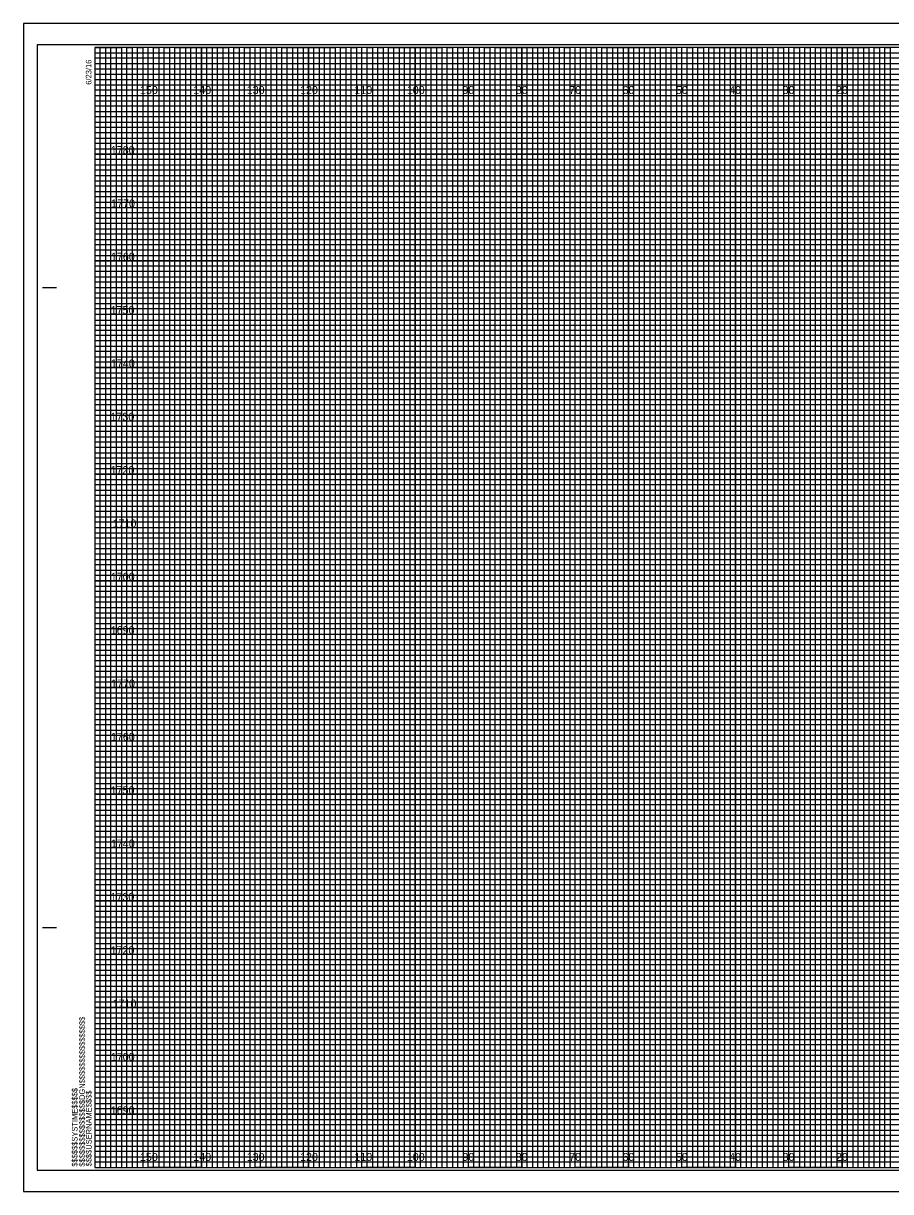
# Model space of a CAD drawing. Extents: x -13 to 1780, y -15 to 3284.
# Drawn here: x 1443.3 to 1605.8, y 205.2 to 424.2 of the extents above; entities that cross this region are included whole.
import ezdxf

# ---------------------------------------------------------------- set-up
doc = ezdxf.new("R2010")
doc.units = 0
for name, color, linetype in [('Prop Retaining Wall', 7, 'Continuous'), ('Prop SS Cut Line', 7, 'Continuous'), ('Prop SS Fill Line', 7, 'Continuous'), ('Prop SS Transition Line', 7, 'Continuous'), ('Prop XS Earthwork Shape', 7, 'Continuous'), ('Prop XS Noise Wall', 7, 'Continuous'), ('Prop XS Station Labels', 7, 'Continuous'), ('Raster_Level_0', 7, 'Continuous'), ('Scratch_Level_3', 7, 'Continuous'), ('Scratch_Level_7', 7, 'Continuous'), ('Typical Bridge Rail CELL', 7, 'Continuous')]:
    doc.layers.add(name, color=color, linetype=linetype)

msp = doc.modelspace()

# ---------------------------------------------------------------- linework, layer by layer
at = {"layer": 'Prop Retaining Wall'}
for p, q in [((1446.88, 374.71), (1449.38, 374.71)), ((1446.98, 374.71), (1449.48, 374.71)), ((1446.88, 254.71), (1449.38, 254.71)), ((1446.98, 254.71), (1449.48, 254.71)), ((1456.68, 209.71), (1456.68, 209.71)), ((1456.68, 209.71), (1456.68, 209.71)), ((1456.68, 209.71), (1456.68, 209.71)), ((1456.68, 209.71), (1456.68, 209.71)), ((1456.68, 209.71), (1456.68, 209.71)), ((1456.68, 209.71), (1456.68, 209.71)), ((1456.68, 209.71), (1456.68, 209.71))]:
    msp.add_line(p, q, dxfattribs=at)
msp.add_lwpolyline([(1776.68, 419.71), (1456.68, 419.71), (1456.68, 209.71), (1776.68, 209.71)], close=True, dxfattribs=at)
at = {"layer": 'Prop SS Cut Line'}
for points in [[(1456.68, 419.71), (1461.68, 419.71), (1461.68, 209.71), (1471.68, 209.71), (1471.68, 419.71), (1481.68, 419.71), (1481.68, 209.71), (1491.68, 209.71), (1491.68, 419.71), (1501.68, 419.71), (1501.68, 209.71), (1511.68, 209.71), (1511.68, 419.71), (1521.68, 419.71), (1521.68, 209.71), (1531.68, 209.71), (1531.68, 419.71), (1541.68, 419.71), (1541.68, 209.71), (1551.68, 209.71), (1551.68, 419.71), (1561.68, 419.71), (1561.68, 209.71), (1571.68, 209.71), (1571.68, 419.71), (1581.68, 419.71), (1581.68, 209.71), (1591.68, 209.71), (1591.68, 419.71), (1601.68, 419.71), (1601.68, 209.71), (1611.68, 209.71)], [(1456.68, 414.71), (1731.68, 414.71)], [(1456.68, 394.71), (1776.68, 394.71), (1776.68, 404.71), (1456.68, 404.71)], [(1456.68, 374.71), (1776.68, 374.71), (1776.68, 384.71), (1456.68, 384.71)], [(1456.68, 354.71), (1776.68, 354.71), (1776.68, 364.71), (1456.68, 364.71)], [(1456.68, 334.71), (1776.68, 334.71), (1776.68, 344.71), (1456.68, 344.71)], [(1456.68, 314.71), (1776.68, 314.71), (1776.68, 324.71), (1456.68, 324.71)], [(1456.68, 294.71), (1776.68, 294.71), (1776.68, 304.71), (1456.68, 304.71)], [(1456.68, 274.71), (1776.68, 274.71), (1776.68, 284.71), (1456.68, 284.71)], [(1456.68, 254.71), (1776.68, 254.71), (1776.68, 264.71), (1456.68, 264.71)], [(1456.68, 234.71), (1776.68, 234.71), (1776.68, 244.71), (1456.68, 244.71)], [(1456.68, 214.71), (1776.68, 214.71), (1776.68, 224.71), (1456.68, 224.71)]]:
    msp.add_lwpolyline(points, dxfattribs=at)
at = {"layer": 'Prop SS Fill Line'}
for p, q in [((1466.68, 419.71), (1456.68, 419.71)), ((1466.68, 209.71), (1466.68, 419.71)), ((1486.68, 419.71), (1476.68, 419.71)), ((1476.68, 419.71), (1476.68, 209.71)), ((1486.68, 209.71), (1486.68, 419.71)), ((1506.68, 419.71), (1496.68, 419.71)), ((1496.68, 419.71), (1496.68, 209.71)), ((1506.68, 209.71), (1506.68, 419.71)), ((1526.68, 419.71), (1516.68, 419.71)), ((1516.68, 419.71), (1516.68, 209.71)), ((1526.68, 209.71), (1526.68, 419.71)), ((1546.68, 419.71), (1536.68, 419.71)), ((1536.68, 419.71), (1536.68, 209.71)), ((1546.68, 209.71), (1546.68, 419.71)), ((1566.68, 419.71), (1556.68, 419.71)), ((1556.68, 419.71), (1556.68, 209.71)), ((1566.68, 209.71), (1566.68, 419.71)), ((1586.68, 419.71), (1576.68, 419.71)), ((1576.68, 419.71), (1576.68, 209.71)), ((1586.68, 209.71), (1586.68, 419.71)), ((1606.68, 419.71), (1596.68, 419.71)), ((1596.68, 419.71), (1596.68, 209.71)), ((1476.68, 209.71), (1466.68, 209.71)), ((1496.68, 209.71), (1486.68, 209.71)), ((1516.68, 209.71), (1506.68, 209.71)), ((1536.68, 209.71), (1526.68, 209.71)), ((1556.68, 209.71), (1546.68, 209.71)), ((1576.68, 209.71), (1566.68, 209.71)), ((1596.68, 209.71), (1586.68, 209.71))]:
    msp.add_line(p, q, dxfattribs=at)
for points in [[(1456.68, 409.71), (1776.68, 409.71), (1776.68, 399.71), (1456.68, 399.71)], [(1456.68, 389.71), (1776.68, 389.71), (1776.68, 379.71), (1456.68, 379.71)], [(1456.68, 369.71), (1776.68, 369.71), (1776.68, 359.71), (1456.68, 359.71)], [(1456.68, 349.71), (1776.68, 349.71), (1776.68, 339.71), (1456.68, 339.71)], [(1456.68, 329.71), (1776.68, 329.71), (1776.68, 319.71), (1456.68, 319.71)], [(1456.68, 309.71), (1776.68, 309.71), (1776.68, 299.71), (1456.68, 299.71)], [(1456.68, 289.71), (1776.68, 289.71), (1776.68, 279.71), (1456.68, 279.71)], [(1456.68, 269.71), (1776.68, 269.71), (1776.68, 259.71), (1456.68, 259.71)], [(1456.68, 249.71), (1776.68, 249.71), (1776.68, 239.71), (1456.68, 239.71)], [(1456.68, 229.71), (1776.68, 229.71), (1776.68, 219.71), (1456.68, 219.71)]]:
    msp.add_lwpolyline(points, dxfattribs=at)
at = {"layer": 'Prop SS Transition Line'}
for p, q in [((1456.68, 418.71), (1716.68, 418.71)), ((1716.68, 417.69), (1456.68, 417.69)), ((1456.68, 417.69), (1456.68, 416.71)), ((1456.68, 416.71), (1716.68, 416.71)), ((1716.68, 415.6), (1456.68, 415.6)), ((1456.68, 415.6), (1456.68, 413.71)), ((1456.68, 413.71), (1776.68, 413.71))]:
    msp.add_line(p, q, dxfattribs=at)
for points in [[(1456.68, 412.71), (1726.68, 412.71), (1776.68, 412.71), (1776.68, 411.71), (1456.68, 411.71)], [(1456.68, 410.71), (1776.68, 410.71), (1776.68, 408.71), (1456.68, 408.71)], [(1456.68, 407.71), (1776.68, 407.71), (1776.68, 406.71), (1456.68, 406.69)], [(1456.68, 405.71), (1776.68, 405.71), (1776.68, 403.71), (1456.68, 403.71)], [(1456.68, 402.71), (1776.68, 402.71), (1776.68, 401.71), (1456.68, 401.71)], [(1456.68, 400.71), (1776.68, 400.71), (1776.68, 398.71), (1456.68, 398.71)], [(1456.68, 397.71), (1776.68, 397.71), (1776.68, 396.71), (1456.68, 396.71)], [(1456.68, 395.71), (1776.68, 395.71), (1776.68, 393.71), (1456.68, 393.71)], [(1456.68, 392.71), (1776.68, 392.71), (1776.68, 391.71), (1456.68, 391.71)], [(1456.68, 390.71), (1776.68, 390.71), (1776.68, 388.71), (1456.68, 388.71)], [(1456.68, 387.71), (1776.68, 387.71), (1776.68, 386.71), (1456.68, 386.71)], [(1456.68, 385.71), (1776.68, 385.71), (1776.68, 383.66), (1776.68, 382.71), (1776.68, 381.71), (1456.68, 381.71)], [(1456.68, 383.71), (1776.68, 383.71), (1776.68, 382.71), (1456.68, 382.71)], [(1456.68, 380.71), (1776.68, 380.71), (1776.68, 378.71), (1456.68, 378.74)], [(1456.68, 378.74), (1776.68, 378.71), (1776.68, 377.71), (1456.68, 377.71)], [(1456.68, 376.71), (1776.68, 376.71), (1776.68, 375.71), (1456.68, 375.71)], [(1456.68, 373.71), (1776.68, 373.71), (1776.68, 372.71), (1456.68, 372.71)], [(1456.68, 371.71), (1776.68, 371.71), (1776.68, 370.71), (1456.68, 370.71)], [(1456.61, 368.6), (1776.68, 368.6), (1776.68, 367.59), (1456.61, 367.59)], [(1456.68, 366.71), (1776.68, 366.71), (1776.68, 365.71), (1456.68, 365.71)], [(1456.68, 363.71), (1776.68, 363.71), (1776.68, 362.71), (1456.68, 362.71)], [(1456.68, 361.71), (1776.68, 361.71), (1776.68, 360.71), (1456.68, 360.71)], [(1456.68, 358.71), (1776.68, 358.71), (1776.68, 357.71), (1456.68, 357.71)], [(1456.68, 356.71), (1776.68, 356.71), (1776.68, 355.71), (1456.68, 355.71)], [(1456.68, 353.71), (1776.68, 353.71), (1776.68, 352.71), (1456.68, 352.71)], [(1456.68, 351.71), (1776.68, 351.71), (1776.68, 350.71), (1456.68, 350.71)], [(1456.68, 348.71), (1776.68, 348.71), (1776.67, 347.69), (1456.68, 347.71)], [(1456.68, 346.71), (1776.68, 346.71), (1776.68, 345.71), (1456.68, 345.71)], [(1456.68, 343.71), (1776.68, 343.71), (1776.68, 342.71), (1456.68, 342.71)], [(1456.68, 341.71), (1776.68, 341.71), (1776.68, 340.71), (1456.68, 340.71)], [(1456.68, 338.71), (1776.68, 338.71), (1776.68, 337.71), (1456.68, 337.71)], [(1456.68, 336.71), (1776.68, 336.71), (1776.68, 335.71), (1456.68, 335.71)], [(1456.68, 333.71), (1776.68, 333.71), (1776.68, 332.71), (1456.68, 332.71)], [(1456.68, 331.71), (1776.68, 331.71), (1776.68, 330.71), (1456.68, 330.71)], [(1456.68, 328.71), (1776.68, 328.71), (1776.68, 327.71), (1456.68, 327.71)], [(1456.68, 326.7), (1776.75, 326.62), (1776.68, 325.71), (1456.68, 325.71)], [(1456.68, 323.71), (1776.68, 323.71), (1776.68, 322.71), (1456.68, 322.71)], [(1456.68, 321.71), (1776.68, 321.71), (1776.68, 320.71), (1456.68, 320.71)], [(1456.68, 318.71), (1776.68, 318.71), (1776.68, 317.71), (1456.68, 317.71)], [(1456.68, 316.71), (1776.68, 316.71), (1776.68, 315.71), (1456.68, 315.71)], [(1456.68, 313.71), (1776.68, 313.71), (1776.68, 312.71), (1456.68, 312.71)], [(1456.68, 311.71), (1776.68, 311.71), (1776.68, 310.71), (1456.68, 310.71)], [(1456.68, 308.71), (1776.68, 308.71), (1776.68, 307.71), (1456.68, 307.71)], [(1456.68, 306.71), (1776.68, 306.71), (1776.68, 305.71), (1456.68, 305.71)], [(1456.68, 303.71), (1776.68, 303.71), (1776.68, 302.71), (1456.68, 302.71)], [(1456.68, 301.71), (1776.68, 301.71), (1776.68, 300.71), (1456.68, 300.71)], [(1456.68, 298.71), (1776.68, 298.71), (1776.68, 297.71), (1456.68, 297.71)], [(1456.68, 296.71), (1776.68, 296.71), (1776.68, 295.71), (1456.68, 295.71)], [(1456.68, 293.71), (1776.68, 293.71), (1776.68, 292.71), (1456.68, 292.71)], [(1456.68, 291.71), (1776.68, 291.71), (1776.68, 290.71), (1456.68, 290.71)], [(1456.68, 288.71), (1776.68, 288.71), (1776.67, 287.69), (1456.68, 287.71)], [(1456.68, 286.71), (1776.68, 286.71), (1776.68, 285.71), (1456.68, 285.71)], [(1456.68, 283.71), (1776.68, 283.71), (1776.68, 282.71), (1456.68, 282.71)], [(1456.68, 281.71), (1776.68, 281.71), (1776.68, 280.71), (1456.68, 280.71)], [(1456.68, 278.71), (1776.68, 278.71), (1776.68, 277.71), (1456.68, 277.71)], [(1456.68, 276.71), (1776.68, 276.71), (1776.68, 275.71), (1456.68, 275.71)], [(1456.68, 273.71), (1776.68, 273.71), (1776.68, 272.71), (1456.68, 272.71)], [(1456.68, 271.71), (1776.68, 271.71), (1776.68, 270.71), (1456.68, 270.71)], [(1456.68, 268.71), (1776.68, 268.71), (1776.68, 267.71), (1456.68, 267.71)], [(1456.68, 266.7), (1776.75, 266.62), (1776.68, 265.71), (1456.68, 265.71)], [(1456.68, 263.71), (1776.68, 263.71), (1776.68, 262.71), (1456.68, 262.71)], [(1456.68, 261.71), (1776.68, 261.71), (1776.68, 260.71), (1456.68, 260.71)], [(1456.68, 258.71), (1776.68, 258.71), (1776.68, 257.71), (1456.68, 257.71)], [(1456.68, 256.71), (1776.68, 256.71), (1776.68, 255.71), (1456.68, 255.71)], [(1456.68, 253.71), (1776.68, 253.71), (1776.68, 252.71), (1456.68, 252.71)], [(1456.68, 251.71), (1776.68, 251.71), (1776.68, 250.71), (1456.68, 250.71)], [(1456.68, 248.71), (1776.68, 248.71), (1776.68, 247.71), (1456.68, 247.71)], [(1456.68, 246.71), (1776.68, 246.71), (1776.68, 245.71), (1456.68, 245.71)], [(1456.68, 243.71), (1776.68, 243.71), (1776.68, 242.71), (1456.68, 242.71)], [(1456.68, 241.71), (1776.68, 241.71), (1776.68, 240.71), (1456.68, 240.71)], [(1456.68, 238.71), (1776.68, 238.71), (1776.68, 237.71), (1456.68, 237.71)], [(1456.68, 236.71), (1776.68, 236.71), (1776.68, 235.71), (1456.68, 235.71)], [(1456.68, 233.71), (1776.68, 233.71), (1776.68, 232.71), (1456.68, 232.71)], [(1456.68, 231.71), (1776.68, 231.71), (1776.68, 230.71), (1456.68, 230.71)], [(1456.68, 228.71), (1776.68, 228.71), (1776.68, 227.71), (1456.68, 227.71)], [(1456.68, 226.71), (1776.68, 226.71), (1776.68, 225.71), (1456.68, 225.71)], [(1456.68, 223.71), (1776.68, 223.71), (1776.68, 222.71), (1456.68, 222.71)], [(1456.68, 221.71), (1776.68, 221.71), (1776.68, 220.71), (1456.68, 220.71)], [(1456.68, 218.71), (1776.68, 218.71), (1776.68, 217.71), (1456.68, 217.71)], [(1456.68, 216.71), (1776.68, 216.71), (1776.68, 215.71), (1456.68, 215.71)], [(1456.68, 213.71), (1776.68, 213.71), (1776.68, 212.71), (1456.68, 212.71)], [(1456.68, 211.71), (1776.68, 211.71), (1776.68, 210.71), (1456.68, 210.71)]]:
    msp.add_lwpolyline(points, dxfattribs=at)
at = {"layer": 'Prop XS Earthwork Shape'}
msp.add_lwpolyline([(1443.28, 205.21), (1779.98, 205.21), (1779.98, 424.21), (1443.28, 424.21)], close=True, dxfattribs=at)
at = {"layer": 'Prop XS Noise Wall'}
for p, q in [((1466.68, 209.71), (1466.68, 419.71)), ((1476.68, 209.71), (1476.68, 419.71)), ((1486.68, 209.71), (1486.68, 419.71)), ((1496.68, 209.71), (1496.68, 419.71)), ((1506.68, 209.71), (1506.68, 419.71)), ((1516.68, 209.71), (1516.68, 419.71)), ((1526.68, 209.71), (1526.68, 419.71)), ((1536.68, 209.71), (1536.68, 419.71)), ((1546.68, 209.71), (1546.68, 419.71)), ((1556.68, 209.71), (1556.68, 419.71)), ((1566.68, 209.71), (1566.68, 419.71)), ((1576.68, 209.71), (1576.68, 419.71)), ((1586.68, 209.71), (1586.68, 419.71)), ((1596.68, 209.71), (1596.68, 419.71)), ((1456.68, 409.71), (1776.68, 409.71)), ((1456.68, 399.71), (1776.68, 399.71)), ((1456.68, 389.71), (1776.68, 389.71)), ((1456.68, 379.71), (1776.68, 379.71)), ((1456.68, 369.71), (1776.68, 369.71)), ((1456.68, 359.71), (1776.68, 359.71)), ((1456.68, 349.71), (1776.68, 349.71)), ((1456.68, 339.71), (1776.68, 339.71)), ((1456.68, 329.71), (1776.68, 329.71)), ((1456.68, 319.71), (1776.68, 319.71)), ((1456.68, 309.71), (1776.68, 309.71)), ((1456.68, 299.71), (1776.68, 299.71)), ((1456.68, 289.71), (1776.68, 289.71)), ((1456.68, 279.71), (1776.68, 279.71)), ((1456.68, 269.71), (1776.68, 269.71)), ((1456.68, 259.71), (1776.68, 259.71)), ((1456.68, 249.71), (1776.68, 249.71)), ((1456.68, 239.71), (1776.68, 239.71)), ((1456.68, 229.71), (1776.68, 229.71)), ((1456.68, 219.71), (1776.68, 219.71))]:
    msp.add_line(p, q, dxfattribs=at)
at = {"layer": 'Prop XS Station Labels'}
for p, q in [((1779.98, 424.21), (1443.28, 424.21)), ((1443.28, 424.21), (1443.28, 205.21)), ((1443.28, 205.21), (1779.98, 205.21))]:
    msp.add_line(p, q, dxfattribs=at)
at = {"layer": 'Scratch_Level_7'}
msp.add_lwpolyline([(1445.88, 209.21), (1779.08, 209.21), (1779.08, 420.21), (1445.88, 420.21)], close=True, dxfattribs=at)
at = {"layer": 'Typical Bridge Rail CELL'}
for points in [[(1456.68, 209.71), (1457.68, 209.71), (1457.68, 419.71), (1458.68, 419.71), (1458.68, 209.71)], [(1458.68, 209.71), (1459.68, 209.71), (1459.68, 419.71), (1460.68, 419.71), (1460.68, 209.71)], [(1461.68, 209.71), (1462.68, 209.71), (1462.68, 419.71), (1463.68, 419.71), (1463.68, 209.71)], [(1463.68, 209.71), (1464.68, 209.71), (1464.68, 419.71), (1465.68, 419.71), (1465.68, 209.71)], [(1466.68, 209.71), (1467.68, 209.71), (1467.68, 419.71), (1468.68, 419.71), (1468.68, 209.71)], [(1468.68, 209.71), (1469.68, 209.71), (1469.68, 419.71), (1470.68, 419.71), (1470.68, 209.71)], [(1471.68, 209.71), (1472.68, 209.71), (1472.68, 419.71), (1473.68, 419.71), (1473.68, 209.71)], [(1473.68, 209.71), (1474.68, 209.71), (1474.68, 419.71), (1475.68, 419.71), (1475.68, 209.71)], [(1476.68, 209.71), (1477.68, 209.71), (1477.68, 419.71), (1478.68, 419.71), (1478.68, 209.71)], [(1478.68, 209.71), (1479.68, 209.71), (1479.68, 419.71), (1480.68, 419.71), (1480.68, 209.71)], [(1481.68, 209.71), (1482.68, 209.71), (1482.68, 419.71), (1483.68, 419.71), (1483.68, 209.71)], [(1483.68, 209.71), (1484.68, 209.71), (1484.68, 419.71), (1485.68, 419.71), (1485.68, 209.71)], [(1486.68, 209.71), (1487.68, 209.71), (1487.68, 419.71), (1488.68, 419.71), (1488.68, 209.71)], [(1488.68, 209.71), (1489.68, 209.71), (1489.68, 419.71), (1490.68, 419.71), (1490.68, 209.71)], [(1491.68, 209.71), (1492.68, 209.71), (1492.68, 419.71), (1493.68, 419.71), (1493.68, 209.71)], [(1493.68, 209.71), (1494.68, 209.71), (1494.68, 419.71), (1495.68, 419.71), (1495.68, 209.71)], [(1496.68, 209.71), (1497.68, 209.71), (1497.68, 419.71), (1498.68, 419.71), (1498.68, 209.71)], [(1498.68, 209.71), (1499.68, 209.71), (1499.68, 419.71), (1500.68, 419.71), (1500.68, 209.71)], [(1501.68, 209.71), (1502.68, 209.71), (1502.68, 419.71), (1503.68, 419.71), (1503.68, 209.71)], [(1503.68, 209.71), (1504.68, 209.71), (1504.68, 419.71), (1505.68, 419.71), (1505.68, 209.71)], [(1506.68, 209.71), (1507.68, 209.71), (1507.68, 419.71), (1508.68, 419.71), (1508.68, 209.71)], [(1508.68, 209.71), (1509.68, 209.71), (1509.68, 419.71), (1510.68, 419.71), (1510.68, 209.71)], [(1511.68, 209.71), (1512.68, 209.71), (1512.68, 419.71), (1513.68, 419.71), (1513.68, 209.71)], [(1513.68, 209.71), (1514.68, 209.71), (1514.68, 419.71), (1515.68, 419.71), (1515.68, 209.71)], [(1516.68, 209.71), (1517.68, 209.71), (1517.68, 419.71), (1518.68, 419.71), (1518.68, 209.71)], [(1518.68, 209.71), (1519.68, 209.71), (1519.68, 419.71), (1520.68, 419.71), (1520.68, 209.71)], [(1521.68, 209.71), (1522.68, 209.71), (1522.68, 419.71), (1523.68, 419.71), (1523.68, 209.71)], [(1523.68, 209.71), (1524.68, 209.71), (1524.68, 419.71), (1525.68, 419.71), (1525.68, 209.71)], [(1526.68, 209.71), (1527.68, 209.71), (1527.68, 419.71), (1528.68, 419.71), (1528.68, 209.71)], [(1528.68, 209.71), (1529.68, 209.71), (1529.68, 419.71), (1530.68, 419.71), (1530.68, 209.71)], [(1531.68, 209.71), (1532.68, 209.71), (1532.68, 419.71), (1533.68, 419.71), (1533.68, 209.71)], [(1533.68, 209.71), (1534.68, 209.71), (1534.68, 419.71), (1535.68, 419.71), (1535.68, 209.71)], [(1536.68, 209.71), (1537.68, 209.71), (1537.68, 419.71), (1538.68, 419.71), (1538.68, 209.71)], [(1538.68, 209.71), (1539.68, 209.71), (1539.68, 419.71), (1540.68, 419.71), (1540.68, 209.71)], [(1541.68, 209.71), (1542.68, 209.71), (1542.68, 419.71), (1543.68, 419.71), (1543.68, 209.71)], [(1543.68, 209.71), (1544.68, 209.71), (1544.68, 419.71), (1545.68, 419.71), (1545.68, 209.71)], [(1546.68, 209.71), (1547.68, 209.71), (1547.68, 419.71), (1548.68, 419.71), (1548.68, 209.71)], [(1548.68, 209.71), (1549.68, 209.71), (1549.68, 419.71), (1550.68, 419.71), (1550.68, 209.71)], [(1551.68, 209.71), (1552.68, 209.71), (1552.68, 419.71), (1553.68, 419.71), (1553.68, 209.71)], [(1553.68, 209.71), (1554.68, 209.71), (1554.68, 419.71), (1555.68, 419.71), (1555.68, 209.71)], [(1556.68, 209.71), (1557.68, 209.71), (1557.68, 419.71), (1558.68, 419.71), (1558.68, 209.71)], [(1558.68, 209.71), (1559.68, 209.71), (1559.68, 419.71), (1560.68, 419.71), (1560.68, 209.71)], [(1561.68, 209.71), (1562.68, 209.71), (1562.68, 419.71), (1563.68, 419.71), (1563.68, 209.71)], [(1563.68, 209.71), (1564.68, 209.71), (1564.68, 419.71), (1565.68, 419.71), (1565.68, 209.71)], [(1566.68, 209.71), (1567.68, 209.71), (1567.68, 419.71), (1568.68, 419.71), (1568.68, 209.71)], [(1568.68, 209.71), (1569.68, 209.71), (1569.68, 419.71), (1570.68, 419.71), (1570.68, 209.71)], [(1571.68, 209.71), (1572.68, 209.71), (1572.68, 419.71), (1573.68, 419.71), (1573.68, 209.71)], [(1573.68, 209.71), (1574.68, 209.71), (1574.68, 419.71), (1575.68, 419.71), (1575.68, 209.71)], [(1576.68, 209.71), (1577.68, 209.71), (1577.68, 419.71), (1578.68, 419.71), (1578.68, 209.71)], [(1578.68, 209.71), (1579.68, 209.71), (1579.68, 419.71), (1580.68, 419.71), (1580.68, 209.71)], [(1581.68, 209.71), (1582.68, 209.71), (1582.68, 419.71), (1583.68, 419.71), (1583.68, 209.71)], [(1583.68, 209.71), (1584.68, 209.71), (1584.68, 419.71), (1585.68, 419.71), (1585.68, 209.71)], [(1586.68, 209.71), (1587.68, 209.71), (1587.68, 419.71), (1588.68, 419.71), (1588.68, 209.71)], [(1588.68, 209.71), (1589.68, 209.71), (1589.68, 419.71), (1590.68, 419.71), (1590.68, 209.71)], [(1591.68, 209.71), (1592.68, 209.71), (1592.68, 419.71), (1593.68, 419.71), (1593.68, 209.71)], [(1593.68, 209.71), (1594.68, 209.71), (1594.68, 419.71), (1595.68, 419.71), (1595.68, 209.71)], [(1596.68, 209.71), (1597.68, 209.71), (1597.68, 419.71), (1598.68, 419.71), (1598.68, 209.71)], [(1598.68, 209.71), (1599.68, 209.71), (1599.68, 419.71), (1600.68, 419.71), (1600.68, 209.71)], [(1601.68, 209.71), (1602.68, 209.71), (1602.68, 419.71), (1603.68, 419.71), (1603.68, 209.71)], [(1603.68, 209.71), (1604.68, 209.71), (1604.68, 419.71), (1605.68, 419.71), (1605.68, 209.71)]]:
    msp.add_lwpolyline(points, dxfattribs=at)

# ---------------------------------------------------------------- texts
at = {"layer": 'Prop Retaining Wall'}
for s, p in [('6/23/16', (1456.03, 412.71)), ('$$$$$$$$$$$$$$$$DGN$$$$$$$$$$$$$$$$', (1454.8, 209.89)), ('$$$$$$SYSTIME$$$$$', (1453.42, 209.89)), ('$$$$USERNAME$$$$', (1456.06, 209.94))]:
    msp.add_text(s, height=1.05, rotation=90, dxfattribs=at).set_placement(p)
at = {"layer": 'Raster_Level_0'}
for s, p in [('150', (1465.12, 410.96)), ('140', (1475.12, 410.96)), ('130', (1485.12, 410.96)), ('120', (1495.12, 410.96)), ('110', (1505.3, 410.96)), ('100', (1515.12, 410.96)), ('90', (1525.53, 410.96)), ('80', (1535.53, 410.96)), ('70', (1545.53, 410.96)), ('60', (1555.53, 410.96)), ('50', (1565.53, 410.96)), ('40', (1575.53, 410.96)), ('30', (1585.53, 410.96)), ('20', (1595.53, 410.96)), ('150', (1465.12, 210.96)), ('140', (1475.12, 210.96)), ('130', (1485.12, 210.96)), ('120', (1495.12, 210.96)), ('110', (1505.3, 210.96)), ('100', (1515.12, 210.96)), ('90', (1525.53, 210.96)), ('80', (1535.53, 210.96)), ('70', (1545.53, 210.96)), ('60', (1555.53, 210.96)), ('50', (1565.53, 210.96)), ('40', (1575.53, 210.96)), ('30', (1585.53, 210.96)), ('20', (1595.53, 210.96))]:
    msp.add_text(s, height=1.5, dxfattribs=at).set_placement(p)
at = {"layer": 'Scratch_Level_3'}
for s, p in [('1780', (1459.66, 399.71)), ('1770', (1459.72, 389.71)), ('1760', (1459.68, 379.71)), ('1750', (1459.63, 369.71)), ('1740', (1459.68, 359.71)), ('1730', (1459.6, 349.71)), ('1720', (1459.61, 339.71)), ('1710', (1459.99, 329.71)), ('1700', (1459.66, 319.71)), ('1690', (1459.65, 309.71)), ('1770', (1459.72, 299.71)), ('1760', (1459.68, 289.71)), ('1750', (1459.63, 279.71)), ('1740', (1459.68, 269.71)), ('1730', (1459.6, 259.71)), ('1720', (1459.61, 249.71)), ('1710', (1459.99, 239.71)), ('1700', (1459.66, 229.71)), ('1690', (1459.65, 219.71))]:
    msp.add_text(s, height=1.5, dxfattribs=at).set_placement(p)

doc.saveas('drawing.dxf')
